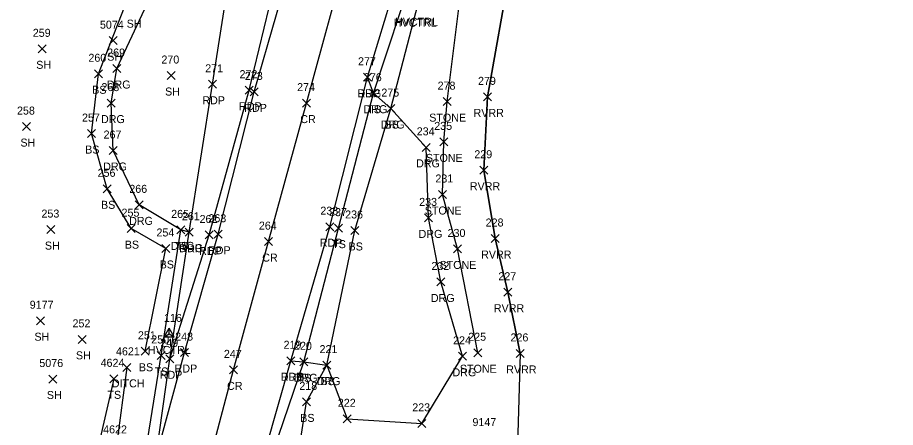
# Model space of a CAD drawing. Extents: x 1482574 to 1485769, y 580696 to 595649.
# Drawn here: x 1483556.5 to 1483775.9, y 584028.9 to 584131.3 of the extents above; entities that cross this region are included whole.
import ezdxf

# ---------------------------------------------------------------- set-up
doc = ezdxf.new("R2010")
doc.units = 0
for name, color, linetype in [('C_A', 7, 'Continuous'), ('C_I', 7, 'Continuous'), ('CPSM', 7, 'Continuous'), ('D_A', 7, 'Continuous'), ('D_I', 7, 'Continuous'), ('D_TIC', 7, 'Continuous'), ('DD', 7, 'Continuous'), ('L_A', 7, 'Continuous'), ('L_I', 7, 'Continuous'), ('L_TIC', 7, 'Continuous'), ('LASF', 7, 'Continuous'), ('LAWE', 7, 'Continuous'), ('LELB', 7, 'Continuous'), ('LSOGP', 7, 'Continuous'), ('P_A', 7, 'Continuous'), ('P_I', 7, 'Continuous'), ('P_TIC', 7, 'Continuous'), ('PET', 7, 'Continuous'), ('PRC', 7, 'Continuous'), ('R_A', 7, 'Continuous'), ('R_I', 7, 'Continuous'), ('R_TIC', 7, 'Continuous'), ('RDG', 7, 'Continuous')]:
    doc.layers.add(name, color=color, linetype=linetype)

msp = doc.modelspace()

# ---------------------------------------------------------------- linework, layer by layer
at = {"layer": 'CPSM'}
for p, q in [((1483593.11, 584051.52), (1483594.36, 584053.68)), ((1483595.61, 584051.52), (1483594.36, 584053.68)), ((1483594.36, 584052.24), (1483594.36, 584053.68)), ((1483593.11, 584051.52), (1483594.36, 584052.24)), ((1483593.11, 584051.52), (1483595.61, 584051.52)), ((1483594.36, 584052.24), (1483594.36, 584052.24)), ((1483594.36, 584052.24), (1483595.61, 584051.52))]:
    msp.add_line(p, q, dxfattribs=at)
at = {"layer": 'D_TIC'}
for points in [[(1483582.83, 584042.89), (1483584.83, 584044.89)], [(1483584.83, 584042.89), (1483582.83, 584044.89)]]:
    msp.add_lwpolyline(points, dxfattribs=at)
at = {"layer": 'DD'}
msp.add_lwpolyline([(1483583.83, 584043.89), (1483581.19, 584024.38), (1483578.76, 584011.33)], dxfattribs=at)
at = {"layer": 'L_TIC'}
for points in [[(1483579.42, 584124.56), (1483581.42, 584126.56)], [(1483581.42, 584124.56), (1483579.42, 584126.56)], [(1483561.67, 584122.52), (1483563.67, 584124.52)], [(1483563.67, 584122.52), (1483561.67, 584124.52)], [(1483575.7, 584116.28), (1483577.7, 584118.28)], [(1483577.7, 584116.28), (1483575.7, 584118.28)], [(1483593.88, 584115.84), (1483595.88, 584117.84)], [(1483595.88, 584115.84), (1483593.88, 584117.84)], [(1483644.46, 584111.42), (1483646.46, 584113.42)], [(1483646.46, 584111.42), (1483644.46, 584113.42)], [(1483672.93, 584110.51), (1483674.93, 584112.51)], [(1483674.93, 584110.51), (1483672.93, 584112.51)], [(1483662.82, 584109.32), (1483664.82, 584111.32)], [(1483664.82, 584109.32), (1483662.82, 584111.32)], [(1483648.78, 584107.58), (1483650.78, 584109.58)], [(1483650.78, 584107.58), (1483648.78, 584109.58)], [(1483557.72, 584103.08), (1483559.72, 584105.08)], [(1483559.72, 584103.08), (1483557.72, 584105.08)], [(1483573.96, 584101.33), (1483575.96, 584103.33)], [(1483575.96, 584101.33), (1483573.96, 584103.33)], [(1483661.98, 584099.25), (1483663.98, 584101.25)], [(1483663.98, 584099.25), (1483661.98, 584101.25)], [(1483672.01, 584092.17), (1483674.01, 584094.17)], [(1483674.01, 584092.17), (1483672.01, 584094.17)], [(1483577.91, 584087.52), (1483579.91, 584089.52)], [(1483579.91, 584087.52), (1483577.91, 584089.52)], [(1483661.71, 584086.1), (1483663.71, 584088.1)], [(1483663.71, 584086.1), (1483661.71, 584088.1)], [(1483583.85, 584077.56), (1483585.85, 584079.56)], [(1483585.85, 584077.56), (1483583.85, 584079.56)], [(1483635.71, 584077.69), (1483637.71, 584079.69)], [(1483637.71, 584077.69), (1483635.71, 584079.69)], [(1483563.83, 584077.33), (1483565.83, 584079.33)], [(1483565.83, 584077.33), (1483563.83, 584079.33)], [(1483596.29, 584077.25), (1483598.29, 584079.25)], [(1483598.29, 584077.25), (1483596.29, 584079.25)], [(1483639.78, 584077.11), (1483641.78, 584079.11)], [(1483641.78, 584077.11), (1483639.78, 584079.11)], [(1483674.83, 584075.1), (1483676.83, 584077.1)], [(1483676.83, 584075.1), (1483674.83, 584077.1)], [(1483592.57, 584072.61), (1483594.57, 584074.61)], [(1483594.57, 584072.61), (1483592.57, 584074.61)], [(1483665.41, 584072.49), (1483667.41, 584074.49)], [(1483667.41, 584072.49), (1483665.41, 584074.49)], [(1483678.01, 584061.67), (1483680.01, 584063.67)], [(1483680.01, 584061.67), (1483678.01, 584063.67)], [(1483561.24, 584054.55), (1483563.24, 584056.55)], [(1483563.24, 584054.55), (1483561.24, 584056.55)], [(1483571.6, 584049.89), (1483573.6, 584051.89)], [(1483573.6, 584049.89), (1483571.6, 584051.89)], [(1483587.37, 584046.91), (1483589.37, 584048.91)], [(1483589.37, 584046.91), (1483587.37, 584048.91)], [(1483591.35, 584045.86), (1483593.35, 584047.86)], [(1483593.35, 584045.86), (1483591.35, 584047.86)], [(1483670.48, 584046.54), (1483672.48, 584048.54)], [(1483672.48, 584046.54), (1483670.48, 584048.54)], [(1483681.09, 584046.37), (1483683.09, 584048.37)], [(1483683.09, 584046.37), (1483681.09, 584048.37)], [(1483627.04, 584044.27), (1483629.04, 584046.27)], [(1483629.04, 584044.27), (1483627.04, 584046.27)], [(1483632.76, 584043.44), (1483634.76, 584045.44)], [(1483634.76, 584043.44), (1483632.76, 584045.44)], [(1483564.33, 584039.97), (1483566.33, 584041.97)], [(1483566.33, 584039.97), (1483564.33, 584041.97)], [(1483579.55, 584040.02), (1483581.55, 584042.02)], [(1483581.55, 584040.02), (1483579.55, 584042.02)], [(1483627.7, 584034.25), (1483629.7, 584036.25)], [(1483629.7, 584034.25), (1483627.7, 584036.25)]]:
    msp.add_lwpolyline(points, dxfattribs=at)
at = {"layer": 'LASF'}
msp.add_lwpolyline([(1483671.48, 584047.54), (1483666.41, 584073.49), (1483662.71, 584087.1), (1483662.98, 584100.25), (1483663.82, 584110.32), (1483667.82, 584142.41), (1483670.21, 584153.21), (1483678.11, 584183), (1483681.32, 584212.31), (1483683.05, 584233.78), (1483685.51, 584245.05), (1483696.78, 584262.57), (1483705.7, 584277.17), (1483710.79, 584290.29), (1483715.48, 584313.49), (1483717.15, 584337.83), (1483717.97, 584359.1), (1483719.66, 584377.86), (1483716.84, 584387.63), (1483711.61, 584397.92), (1483702.45, 584409.36), (1483691.17, 584424.34), (1483688.63, 584428.24), (1483691.21, 584429.95)], dxfattribs=at)
at = {"layer": 'LAWE'}
msp.add_lwpolyline([(1483682.09, 584047.37), (1483679.01, 584062.67), (1483675.83, 584076.1), (1483673.01, 584093.17), (1483673.93, 584111.51), (1483679.64, 584143.96), (1483684.39, 584184.99), (1483689.2, 584212.44), (1483691.45, 584231.01), (1483699.73, 584252.81), (1483710.3, 584271.09), (1483715.87, 584279.92), (1483724.32, 584288.73), (1483732.24, 584294.29), (1483734.05, 584295.82), (1483747.44, 584305.84), (1483760.72, 584319.04), (1483775.88, 584327.57)], dxfattribs=at)
at = {"layer": 'LELB'}
for points in [[(1483609.7, 583968.11), (1483614.54, 583983.93), (1483615.47, 583999.91), (1483618.2, 584010.03), (1483620.48, 584023), (1483628.04, 584045.27), (1483636.71, 584078.69), (1483645.46, 584112.42), (1483655.7, 584143.54), (1483665.33, 584182.72), (1483668.64, 584191.09), (1483674.48, 584213.68), (1483679.56, 584233.01), (1483687.36, 584264.16), (1483694.8, 584284.35), (1483705.09, 584327.19), (1483710.94, 584361.26), (1483712.22, 584376.12), (1483713.45, 584382.29)], [(1483588.37, 584047.91), (1483593.57, 584073.61), (1483584.85, 584078.56), (1483578.91, 584088.52), (1483574.96, 584102.33), (1483576.7, 584117.28), (1483592.06, 584156.66), (1483602.05, 584187.38), (1483609.21, 584200.53), (1483612.69, 584202.43), (1483616.91, 584240.61), (1483624.14, 584278.36), (1483628.31, 584304.69), (1483631.95, 584339.18), (1483630.26, 584349.99), (1483629.18, 584362.71), (1483627.9, 584362.85)], [(1483618.2, 584010.03), (1483623.29, 584011.26), (1483626.83, 584023.46), (1483628.7, 584035.25), (1483633.76, 584044.44), (1483640.78, 584078.11), (1483649.78, 584108.58), (1483658.6, 584142.62), (1483667.1, 584181.27), (1483671.18, 584190.09), (1483677.27, 584212.88)], [(1483579.41, 583973.69), (1483585.96, 584007.72), (1483588.33, 584021.43), (1483592.35, 584046.86), (1483597.29, 584078.25)], [(1483580.55, 584041.02), (1483574.85, 584016.43), (1483567.47, 583987.63), (1483562.38, 583956.41), (1483560.62, 583938.4), (1483564.88, 583932.32), (1483570.68, 583938.41), (1483577.09, 583965.84)]]:
    msp.add_lwpolyline(points, dxfattribs=at)
at = {"layer": 'LSOGP'}
msp.add_lwpolyline([(1483715.87, 584279.92), (1483710.3, 584271.09), (1483699.73, 584252.81), (1483691.45, 584231.01), (1483689.2, 584212.44), (1483684.39, 584184.99), (1483679.64, 584143.96), (1483673.93, 584111.51), (1483673.01, 584093.17), (1483675.83, 584076.1), (1483679.01, 584062.67), (1483682.09, 584047.37), (1483681.18, 584015.9)], dxfattribs=at)
at = {"layer": 'P_TIC'}
for points in [[(1483642.94, 584115.41), (1483644.94, 584117.41)], [(1483644.94, 584115.41), (1483642.94, 584117.41)], [(1483604.18, 584113.65), (1483606.18, 584115.65)], [(1483606.18, 584113.65), (1483604.18, 584115.65)], [(1483613.34, 584112.18), (1483615.34, 584114.18)], [(1483615.34, 584112.18), (1483613.34, 584114.18)], [(1483614.66, 584111.76), (1483616.66, 584113.76)], [(1483616.66, 584111.76), (1483614.66, 584113.76)], [(1483627.72, 584108.95), (1483629.72, 584110.95)], [(1483629.72, 584108.95), (1483627.72, 584110.95)], [(1483633.53, 584078.05), (1483635.53, 584080.05)], [(1483635.53, 584078.05), (1483633.53, 584080.05)], [(1483598.41, 584076.68), (1483600.41, 584078.68)], [(1483600.41, 584076.68), (1483598.41, 584078.68)], [(1483603.39, 584075.98), (1483605.39, 584077.98)], [(1483605.39, 584075.98), (1483603.39, 584077.98)], [(1483605.6, 584076.17), (1483607.6, 584078.17)], [(1483607.6, 584076.17), (1483605.6, 584078.17)], [(1483618.21, 584074.32), (1483620.21, 584076.32)], [(1483620.21, 584074.32), (1483618.21, 584076.32)], [(1483593.54, 584045.02), (1483595.54, 584047.02)], [(1483595.54, 584045.02), (1483593.54, 584047.02)], [(1483593.54, 584045.02), (1483595.54, 584047.02)], [(1483595.54, 584045.02), (1483593.54, 584047.02)], [(1483597.25, 584046.59), (1483599.25, 584048.59)], [(1483599.25, 584046.59), (1483597.25, 584048.59)], [(1483623.77, 584044.54), (1483625.77, 584046.54)], [(1483625.77, 584044.54), (1483623.77, 584046.54)], [(1483609.42, 584042.26), (1483611.42, 584044.26)], [(1483611.42, 584042.26), (1483609.42, 584044.26)]]:
    msp.add_lwpolyline(points, dxfattribs=at)
at = {"layer": 'PET'}
for points in [[(1483581.83, 583972.99), (1483588.38, 584007.28), (1483591.08, 584021.15), (1483598.25, 584047.59), (1483606.6, 584077.17), (1483615.66, 584112.76), (1483626.75, 584151.48), (1483639.2, 584196.36), (1483648.5, 584230.6), (1483659.8, 584272.39), (1483666.33, 584295.08), (1483675.64, 584335.04), (1483684.8, 584386.22), (1483696.48, 584384.63), (1483708.99, 584382.82)], [(1483606.55, 583968.55), (1483613.49, 584003.98), (1483618.43, 584023.3), (1483624.77, 584045.54), (1483634.53, 584079.05), (1483643.94, 584116.41), (1483652.44, 584144.5), (1483663.26, 584189.19), (1483675.01, 584230.16), (1483684.23, 584265.33), (1483690.21, 584285.32), (1483701.13, 584329.73), (1483708.99, 584382.82)], [(1483591.08, 584021.15), (1483594.54, 584046.02), (1483599.41, 584077.68), (1483605.18, 584114.65), (1483611.16, 584152.51), (1483617.88, 584200.25), (1483625.23, 584246.59), (1483629.42, 584277.16)], [(1483594.54, 584046.02), (1483604.39, 584076.98), (1483614.34, 584113.18), (1483620.6, 584139.06), (1483624.66, 584151.24), (1483637.48, 584196.8), (1483645.22, 584230.89), (1483647.15, 584246.07), (1483652.12, 584273.97)]]:
    msp.add_lwpolyline(points, dxfattribs=at)
at = {"layer": 'PRC'}
msp.add_lwpolyline([(1483594.14, 583970.96), (1483600.75, 584006.37), (1483610.42, 584043.26), (1483619.21, 584075.32), (1483628.72, 584109.95), (1483639.31, 584148.68), (1483651.07, 584192.24), (1483662.56, 584233.23), (1483672.36, 584268.88), (1483678.88, 584291.31), (1483688.34, 584333), (1483696.48, 584384.63)], dxfattribs=at)
at = {"layer": 'R_TIC'}
for points in [[(1483580.31, 584117.59), (1483582.31, 584119.59)], [(1483582.31, 584117.59), (1483580.31, 584119.59)], [(1483642.94, 584115.41), (1483644.94, 584117.41)], [(1483644.94, 584115.41), (1483642.94, 584117.41)], [(1483644.46, 584111.42), (1483646.46, 584113.42)], [(1483646.46, 584111.42), (1483644.46, 584113.42)], [(1483578.85, 584108.95), (1483580.85, 584110.95)], [(1483580.85, 584108.95), (1483578.85, 584110.95)], [(1483648.78, 584107.58), (1483650.78, 584109.58)], [(1483650.78, 584107.58), (1483648.78, 584109.58)], [(1483657.6, 584097.89), (1483659.6, 584099.89)], [(1483659.6, 584097.89), (1483657.6, 584099.89)], [(1483579.4, 584097.09), (1483581.4, 584099.09)], [(1483581.4, 584097.09), (1483579.4, 584099.09)], [(1483585.88, 584083.51), (1483587.88, 584085.51)], [(1483587.88, 584083.51), (1483585.88, 584085.51)], [(1483658.22, 584080.25), (1483660.22, 584082.25)], [(1483660.22, 584080.25), (1483658.22, 584082.25)], [(1483596.29, 584077.25), (1483598.29, 584079.25)], [(1483598.29, 584077.25), (1483596.29, 584079.25)], [(1483598.41, 584076.68), (1483600.41, 584078.68)], [(1483600.41, 584076.68), (1483598.41, 584078.68)], [(1483661.3, 584064.23), (1483663.3, 584066.23)], [(1483663.3, 584064.23), (1483661.3, 584066.23)], [(1483623.77, 584044.54), (1483625.77, 584046.54)], [(1483625.77, 584044.54), (1483623.77, 584046.54)], [(1483666.69, 584045.65), (1483668.69, 584047.65)], [(1483668.69, 584045.65), (1483666.69, 584047.65)], [(1483627.04, 584044.27), (1483629.04, 584046.27)], [(1483629.04, 584044.27), (1483627.04, 584046.27)], [(1483632.76, 584043.44), (1483634.76, 584045.44)], [(1483634.76, 584043.44), (1483632.76, 584045.44)], [(1483637.9, 584030.02), (1483639.9, 584032.02)], [(1483639.9, 584030.02), (1483637.9, 584032.02)], [(1483656.49, 584028.89), (1483658.49, 584030.89)], [(1483658.49, 584028.89), (1483656.49, 584030.89)]]:
    msp.add_lwpolyline(points, dxfattribs=at)
at = {"layer": 'RDG'}
for points in [[(1483599.41, 584077.68), (1483597.29, 584078.25), (1483586.88, 584084.51), (1483580.4, 584098.09), (1483579.85, 584109.95), (1483581.31, 584118.59), (1483598.41, 584155.09), (1483605.14, 584185.92), (1483614.17, 584199.37), (1483617.88, 584200.25)], [(1483624.77, 584045.54), (1483628.04, 584045.27), (1483633.76, 584044.44), (1483638.9, 584031.02), (1483657.49, 584029.89), (1483667.69, 584046.65), (1483662.3, 584065.23), (1483659.22, 584081.25), (1483658.6, 584098.89), (1483649.78, 584108.58), (1483645.46, 584112.42), (1483643.94, 584116.41)]]:
    msp.add_lwpolyline(points, dxfattribs=at)

# ---------------------------------------------------------------- texts
at = {"layer": 'C_A'}
for p in [(1483650.51, 584129.03), (1483650.85, 584129.28), (1483589.06, 584047.24)]:
    msp.add_text('HVCTRL', height=2, dxfattribs=at).set_placement(p)
at = {"layer": 'C_I'}
msp.add_text('116', height=2, dxfattribs=at).set_placement((1483593.08, 584055.24))
at = {"layer": 'D_A'}
msp.add_text('DITCH', height=2, dxfattribs=at).set_placement((1483580.06, 584038.89))
at = {"layer": 'D_I'}
for s, p in [('4621', (1483581.09, 584046.89)), ('4622', (1483577.88, 584027.38))]:
    msp.add_text(s, height=2, dxfattribs=at).set_placement(p)
at = {"layer": 'L_A'}
for s, p in [('SH', (1483583.76, 584128.81)), ('SH', (1483578.91, 584120.56)), ('SH', (1483561.16, 584118.52)), ('BS', (1483575.14, 584112.28)), ('SH', (1483593.37, 584111.84)), ('TS', (1483643.87, 584107.42)), ('RVRR', (1483670.44, 584106.51)), ('STONE', (1483659.37, 584105.32)), ('BS', (1483648.22, 584103.58)), ('SH', (1483557.21, 584099.08)), ('BS', (1483573.4, 584097.33)), ('STONE', (1483658.53, 584095.25)), ('RVRR', (1483669.52, 584088.17)), ('BS', (1483577.35, 584083.52)), ('STONE', (1483658.25, 584082.1)), ('SH', (1483563.32, 584073.33)), ('BS', (1483583.29, 584073.56)), ('TS', (1483595.7, 584073.25)), ('TS', (1483635.12, 584073.69)), ('BS', (1483639.22, 584073.11)), ('RVRR', (1483672.34, 584071.1)), ('BS', (1483592.01, 584068.61)), ('STONE', (1483661.95, 584068.49)), ('RVRR', (1483675.52, 584057.67)), ('SH', (1483560.72, 584050.55)), ('SH', (1483571.08, 584045.89)), ('BS', (1483586.81, 584042.91)), ('STONE', (1483667.03, 584042.54)), ('RVRR', (1483678.61, 584042.37)), ('TS', (1483590.76, 584041.86)), ('TS', (1483626.45, 584040.27)), ('BS', (1483632.2, 584039.44)), ('SH', (1483563.82, 584035.97)), ('TS', (1483578.96, 584036.02)), ('BS', (1483627.14, 584030.25))]:
    msp.add_text(s, height=2, dxfattribs=at).set_placement(p)
at = {"layer": 'L_I'}
for s, p in [('5074', (1483577.08, 584128.56)), ('259', (1483560.3, 584126.52)), ('260', (1483574.2, 584120.28)), ('270', (1483592.44, 584119.84)), ('276', (1483643.04, 584115.42)), ('278', (1483661.46, 584113.32)), ('279', (1483671.56, 584114.51)), ('275', (1483647.41, 584111.58)), ('258', (1483556.36, 584107.08)), ('257', (1483572.6, 584105.33)), ('235', (1483660.62, 584103.25)), ('229', (1483670.64, 584096.17)), ('256', (1483576.5, 584091.52)), ('231', (1483660.91, 584090.1)), ('253', (1483562.47, 584081.33)), ('255', (1483582.48, 584081.56)), ('265', (1483594.88, 584081.25)), ('237', (1483634.34, 584081.69)), ('236', (1483638.36, 584081.11)), ('228', (1483673.47, 584079.1)), ('254', (1483591.21, 584076.61)), ('230', (1483663.96, 584076.49)), ('227', (1483676.65, 584065.67)), ('9177', (1483559.54, 584058.55)), ('252', (1483570.23, 584053.89)), ('251', (1483586.57, 584050.91)), ('250', (1483589.9, 584049.86)), ('225', (1483669.12, 584050.54)), ('226', (1483679.68, 584050.37)), ('220', (1483625.59, 584048.27)), ('221', (1483631.96, 584047.44)), ('5076', (1483561.94, 584043.97)), ('4624', (1483577.25, 584044.02)), ('218', (1483626.91, 584038.25)), ('9147', (1483670.17, 584029.21))]:
    msp.add_text(s, height=2, dxfattribs=at).set_placement(p)
at = {"layer": 'P_A'}
for s, p in [('RDP', (1483641.43, 584111.41)), ('RDP', (1483602.67, 584109.65)), ('RDP', (1483611.82, 584108.18)), ('RDP', (1483613.15, 584107.76)), ('CR', (1483627.15, 584104.95)), ('RDP', (1483632.01, 584074.05)), ('RDP', (1483596.9, 584072.68)), ('RDP', (1483601.87, 584071.98)), ('RDP', (1483604.09, 584072.17)), ('CR', (1483617.64, 584070.32)), ('RDP', (1483595.74, 584042.59)), ('RDP', (1483592.03, 584041.02)), ('RDP', (1483592.03, 584041.02)), ('RDP', (1483622.26, 584040.54)), ('CR', (1483608.86, 584038.26))]:
    msp.add_text(s, height=2, dxfattribs=at).set_placement(p)
at = {"layer": 'P_I'}
for s, p in [('277', (1483641.58, 584119.41)), ('271', (1483603.39, 584117.65)), ('272', (1483611.97, 584116.18)), ('273', (1483613.3, 584115.76)), ('274', (1483626.35, 584112.95)), ('238', (1483632.16, 584082.05)), ('261', (1483597.56, 584080.68)), ('262', (1483601.98, 584079.98)), ('263', (1483604.19, 584080.17)), ('264', (1483616.8, 584078.32)), ('249', (1483592.17, 584049.02)), ('249', (1483592.17, 584049.02)), ('248', (1483595.89, 584050.59)), ('219', (1483622.97, 584048.54)), ('247', (1483608.06, 584046.26))]:
    msp.add_text(s, height=2, dxfattribs=at).set_placement(p)
at = {"layer": 'R_A'}
for p in [(1483578.79, 584113.59), (1483641.43, 584111.41), (1483642.95, 584107.42), (1483577.34, 584104.95), (1483647.27, 584103.58), (1483577.89, 584093.09), (1483656.09, 584093.89), (1483584.37, 584079.51), (1483656.71, 584076.25), (1483594.78, 584073.25), (1483596.9, 584072.68), (1483659.78, 584060.23), (1483622.26, 584040.54), (1483625.53, 584040.27), (1483665.18, 584041.65), (1483631.25, 584039.44)]:
    msp.add_text('DRG', height=2, dxfattribs=at).set_placement(p)
at = {"layer": 'R_I'}
for s, p in [('269', (1483578.89, 584121.59)), ('277', (1483641.58, 584119.41)), ('276', (1483643.04, 584115.42)), ('268', (1483577.45, 584112.95)), ('275', (1483647.41, 584111.58)), ('234', (1483656.24, 584101.89)), ('267', (1483577.99, 584101.09)), ('266', (1483584.42, 584087.51)), ('233', (1483656.86, 584084.25)), ('265', (1483594.88, 584081.25)), ('261', (1483597.56, 584080.68)), ('232', (1483659.93, 584068.23)), ('224', (1483665.33, 584049.65)), ('219', (1483622.97, 584048.54)), ('220', (1483625.59, 584048.27)), ('221', (1483631.96, 584047.44)), ('222', (1483636.53, 584034.02)), ('223', (1483655.13, 584032.89))]:
    msp.add_text(s, height=2, dxfattribs=at).set_placement(p)

doc.saveas('drawing.dxf')
